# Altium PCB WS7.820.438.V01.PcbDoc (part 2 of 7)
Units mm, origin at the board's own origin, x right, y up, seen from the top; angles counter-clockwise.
Board outline 143.01 x 224 mm, 4 copper layers (Top Layer, G2, S3, Bottom Layer); 863 components, 638 nets, 2623 pads, 4664 vias.
Unrouted connection lines stored in the file: 16.
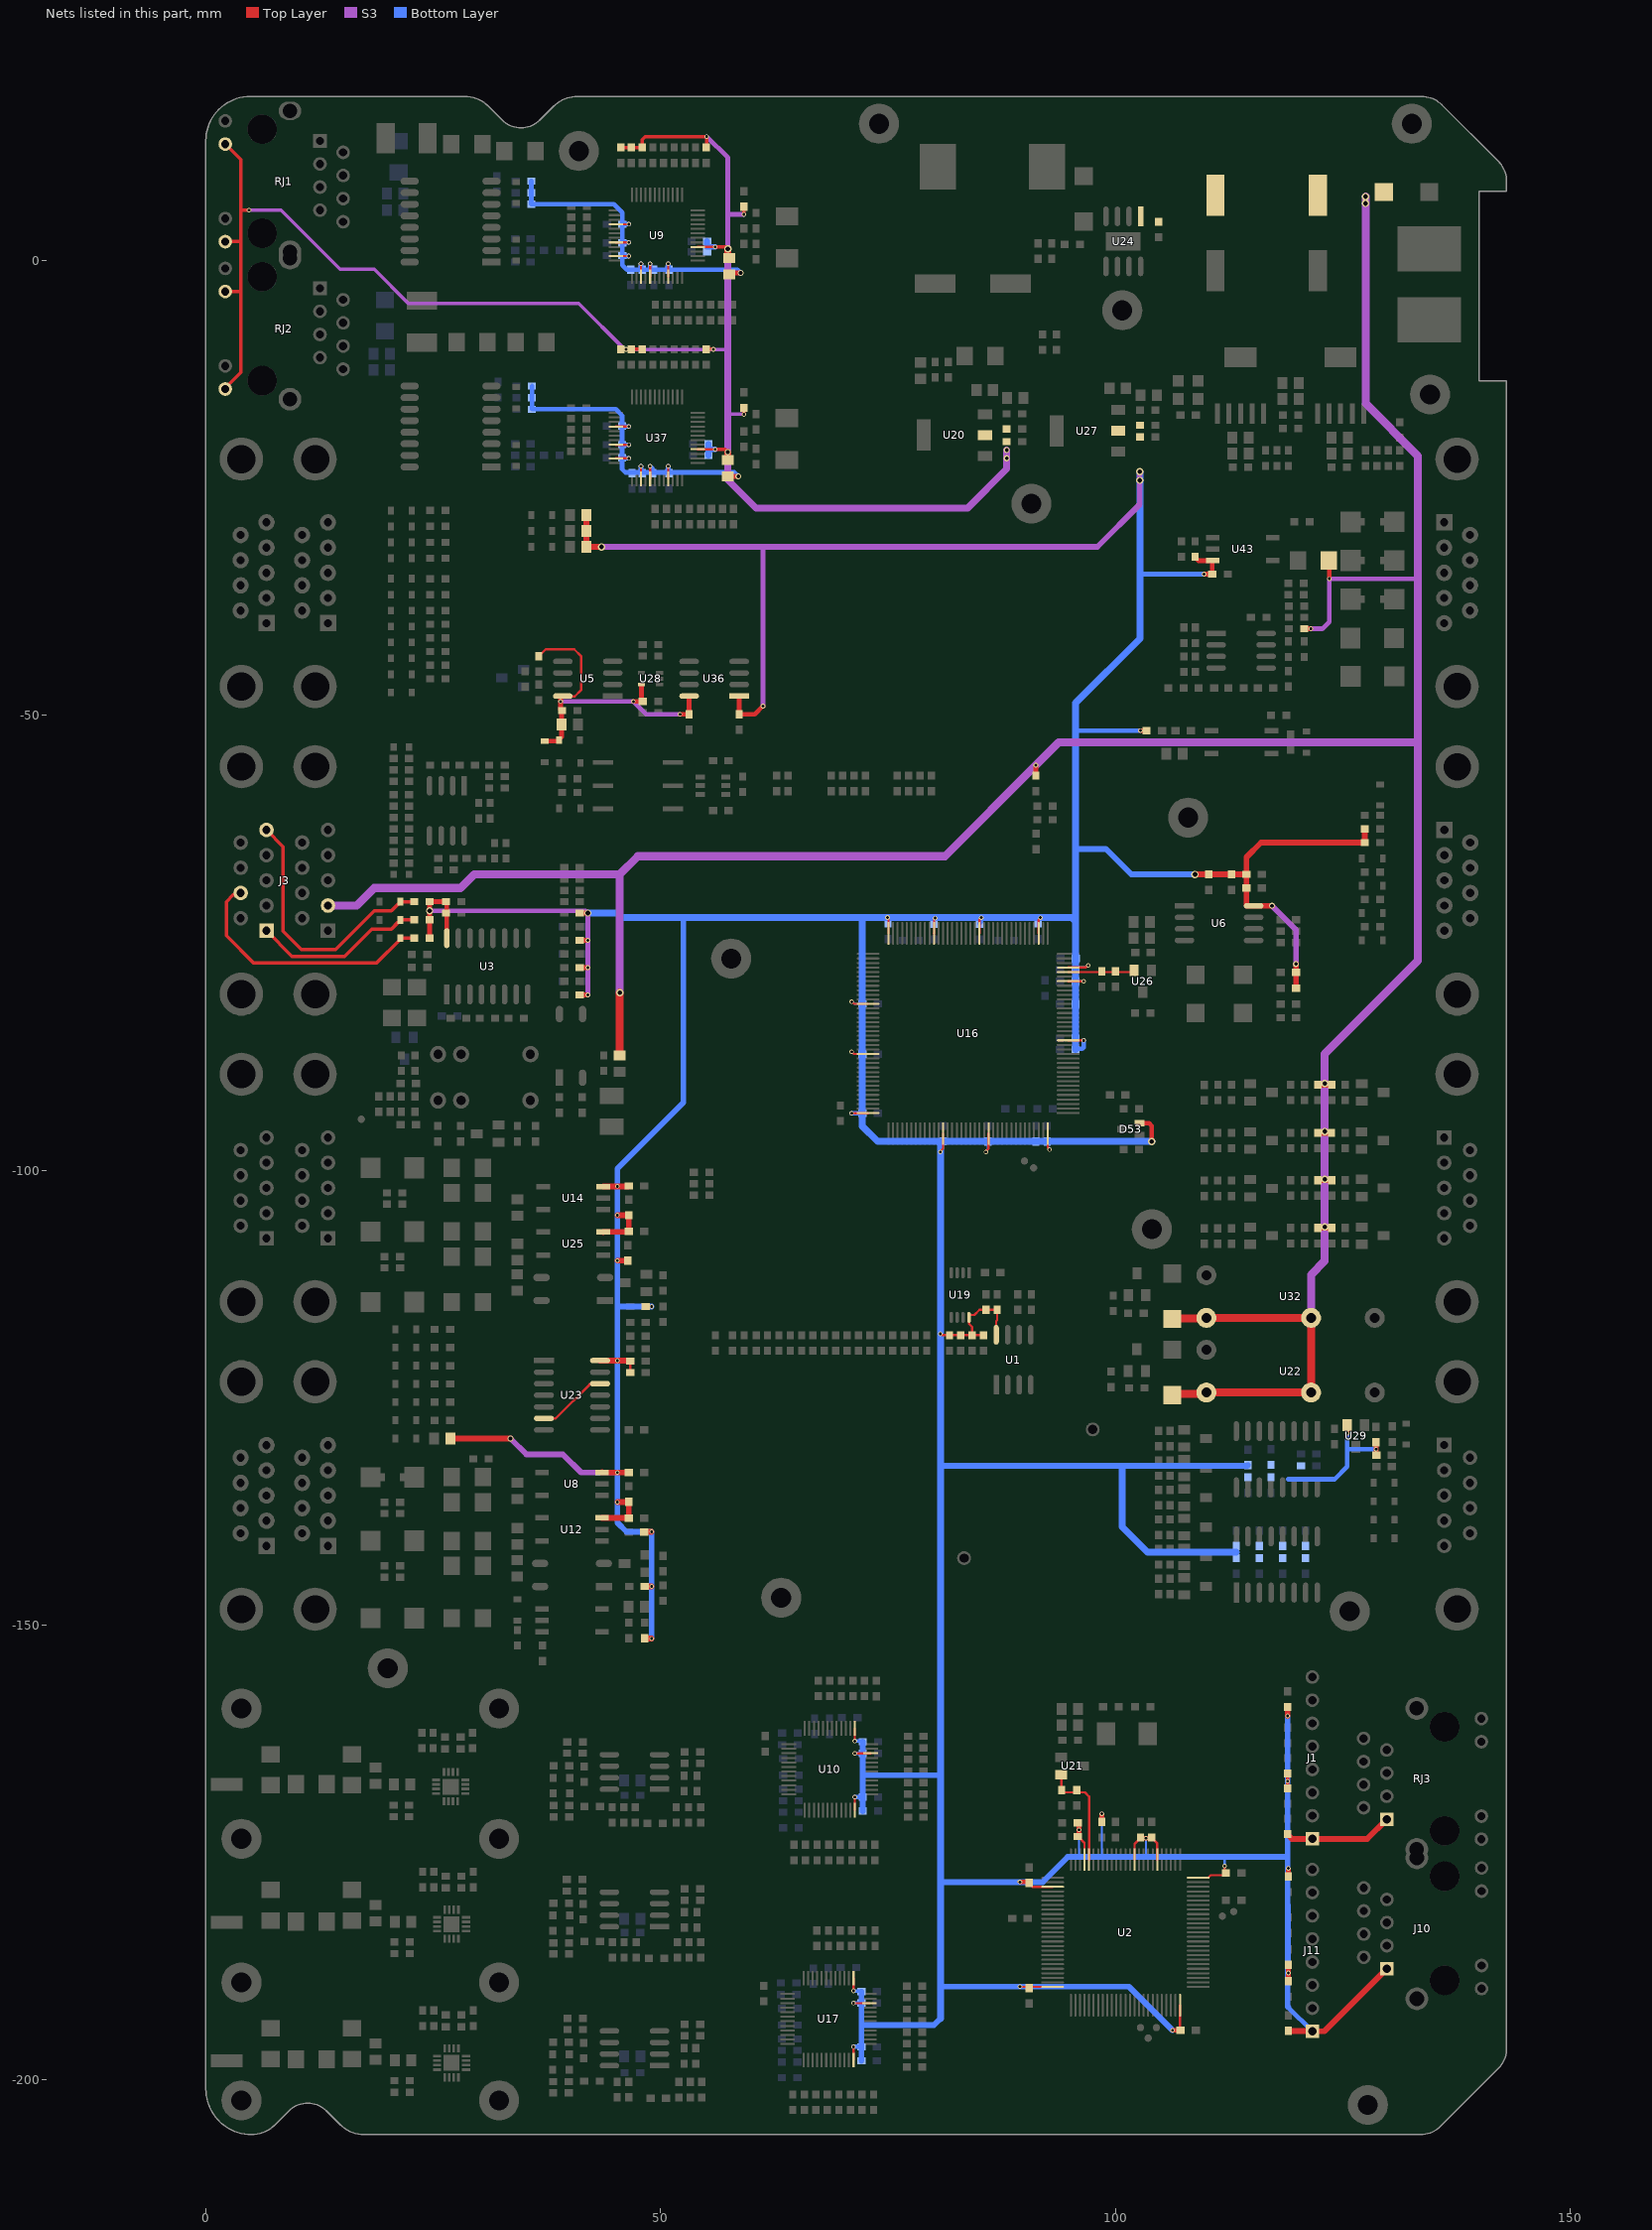
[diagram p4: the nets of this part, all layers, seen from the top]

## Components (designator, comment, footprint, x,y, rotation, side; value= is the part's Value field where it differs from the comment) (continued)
X2 "25M" CRY2SM-6R0X3R5 63.9,2.522 r270 top
X3 "40M" CRY4SM-5R0x7R0 111.403,-80.636 r180 top
X5 "25M" CRY2SM-6R0x3R5 63.886,-19.66 r270 top

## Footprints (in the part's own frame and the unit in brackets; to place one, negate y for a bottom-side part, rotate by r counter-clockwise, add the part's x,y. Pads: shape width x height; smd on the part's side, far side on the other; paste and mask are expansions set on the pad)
C0603#1 [mm]
  rect 0.9x0.8 smd: 1(-0.85,0) 2(0.85,0)
  silkscreen extent -1.47,-0.55 1.47,0.55
C0603#2 [mm]
  rect 0.9x0.8 smd: 1(0.85,0) 2(-0.85,0)
  silkscreen extent -1.47,-0.55 1.47,0.55
C0805#1 [mm]
  rect 1.1x1.3 smd: 1(-0.9,0) 2(0.9,0)
  silkscreen extent -1.57,-0.76 1.57,0.76
C0805#2 [mm]
  rect 1.2x1.3 smd: 1(-1.1,0) 2(1.1,0)
  silkscreen extent -1.88,-0.84 1.88,0.84
C1206 [mm]
  rect 1.8x2 smd: 1(-1.7,0) 2(1.7,0)
  silkscreen extent -2.79,-1.19 2.79,1.19
C1210 [mm]
  rect 1.8x2.6 smd: 1(-1.7,0) 2(1.7,0)
  silkscreen extent -2.82,-1.52 2.82,1.52
CR2032 [mm] "纽扣电池"
  round 1.524 hole 1: 1(10,0) 2(-10,0)
  silkscreen extent -12.85,-11.05 11.45,11.05
CRY2SM-6R0x3R5 [mm]
  rect 2x2.5 smd: 1(-2.3,0) 2(2.3,0)
  silkscreen extent -3.4,-2.03 3.4,1.97
CRY2SM-6R0X3R5 [mm]
  rect 2x2.5 smd: 1(-2.3,0) 2(2.3,0)
  silkscreen extent -3.4,-2.03 3.4,1.97
CRY4SM-5R0x7R0 [mm]
  rect 2x2 smd: 1(-2.6,-2.1) 2(2.6,-2.1) 3(2.6,2.1) 4(-2.6,2.1)
  silkscreen extent -3.81,-4.02 3.81,3.33
D1812 [mm]
  rect 2x3.3 smd: 1(-2.3,0) 2(2.3,0)
  silkscreen extent -3.48,-1.85 3.48,1.85
DB2TM-VM [mm] "DB2"
  rect 5x7 smd: 1(-3.9,0) 2(3.9,0)
  Top Overlay keep-out lines w0.1: -1.298,2.812 -5.698,2.812
  silkscreen extent -15.4,-1.19 15.4,19.81
DB9TM-RF#1 [mm] "90度弯针DB9，焊接在板子上"
  rect 1.6x1.6 hole 0.9: 1(0,0)
  round 1.6 hole 0.9: 2(-2.77,0) 3(-5.54,0) 4(-8.31,0) 5(-11.08,0) 6(-1.385,-2.84) 7(-4.155,-2.84) 8(-6.925,-2.84) 9(-9.695,-2.84)
  round 4.76 hole 3: 10(6.955,-1.42) 11(-18.035,-1.42)
  silkscreen extent -20.94,-16.92 9.86,1.48
DB9TM-RF#2 [mm] "90度弯针DB9，焊接在板子上"
  rect 1.8x1.8 hole 0.9: 1(0,0)
  round 1.8 hole 0.9: 2(-2.77,0) 3(-5.54,0) 4(-8.31,0) 5(-11.08,0) 6(-1.385,-2.84) 7(-4.155,-2.84) 8(-6.925,-2.84) 9(-9.695,-2.84)
  round 4.76 hole 3: 10(6.955,-1.42) 11(-18.035,-1.42)
  silkscreen extent -20.94,-16.92 9.86,1.48
DB9TM-RF-双胞胎#1 [mm] "90度弯针DB9，焊接在板子上"
  rect 1.6x1.6 hole 0.9: A1(5.54,-1.96) B1(5.54,4.8)
  round 1.6 hole 0.9: A2(2.77,-1.96) A3(0,-1.96) A4(-2.77,-1.96) A5(-5.54,-1.96) A6(4.155,-4.8) A7(1.385,-4.8) A8(-1.385,-4.8) A9(-4.155,-4.8) B2(2.77,4.8) B3(0,4.8) B4(-2.77,4.8) B5(-5.54,4.8) B6(4.155,1.96) B7(1.385,1.96) B8(-1.385,1.96) B9(-4.155,1.96)
  round 4.76 hole 3.1: A10(12.495,-4.72) A11(-12.495,-4.72) B10(12.495,3.38) B11(-12.495,3.38)
  silkscreen extent -15.4,-18.88 15.4,6.37
DB9TM-RF-双胞胎#2 [mm] "90度弯针DB9，焊接在板子上"
  rect 1.8x1.8 hole 0.9: A1(5.54,-1.96) B1(5.54,4.8)
  round 1.8 hole 0.9: A2(2.77,-1.96) A3(0,-1.96) A4(-2.77,-1.96) A5(-5.54,-1.96) A6(4.155,-4.8) A7(1.385,-4.8) A8(-1.385,-4.8) A9(-4.155,-4.8) B2(2.77,4.8) B3(0,4.8) B4(-2.77,4.8) B5(-5.54,4.8) B6(4.155,1.96) B7(1.385,1.96) B8(-1.385,1.96) B9(-4.155,1.96)
  round 4.76 hole 3.1: A10(12.495,-4.72) A11(-12.495,-4.72) B10(12.495,3.38) B11(-12.495,3.38)
  silkscreen extent -15.4,-18.88 15.4,6.37
DO-214AA [mm]
  rect 2.2x2.2 smd: 1(-2.4,0)
  rect 2.2x2.3 smd: 2(2.4,0)
  silkscreen extent -2.35,-1.97 2.35,1.97
DO-214AC [mm]
  rect 2x2 smd: 1(-2.5,0) 2(2.5,0)
  silkscreen extent -3.04,-1.49 3.04,1.49
ECAP2SM_10R4x10R4 [mm]
  rect 4.5x2 smd: 1(-4.15,0) 2(4.15,0)
  silkscreen extent -6.16,-5.21 5.08,5.21
G5NB-1A-E-DC24-20R4X7 [mm]
  round 2.2 hole 1.1: 1(-9.25,-2.35) 2(2.25,-2.35) 3(9.25,-2.35) 4(-9.25,2.35)
  silkscreen extent -10.41,-3.5 10.41,3.5
G5V-1-5VDC [mm]
  round 1.8 hole 1: 1(-5.08,-2.54) 2(-2.54,-2.54) 5(5.08,-2.54) 6(5.08,2.54) 9(-2.54,2.54) 10(-5.08,2.54)
  silkscreen extent -6.3,-3.81 6.3,3.8
L0603 [mm]
  rect 0.9x0.8 smd: 1(0.85,0) 2(-0.85,0)
  silkscreen extent -1.47,-0.55 1.47,0.55
L0805 [mm]
  rect 1.1x1.3 smd: 1(-0.9,0) 2(0.9,0)
  silkscreen extent -1.57,-0.76 1.57,0.76
L1206 [mm]
  rect 1.8x2 smd: 1(-1.7,0) 2(1.7,0)
  silkscreen extent -2.79,-1.19 2.79,1.19
LQFP100_0R5_14x14 [mm]
  rect 0.22x2.5 smd: 1(6.326,7.865)
  oval 0.22x2.5 smd: 2(5.826,7.865) 3(5.326,7.865) 4(4.826,7.865) 5(4.326,7.865) 6(3.826,7.865) 7(3.326,7.865) 8(2.826,7.865) 9(2.326,7.865) 10(1.826,7.865) 11(1.326,7.865) 12(0.826,7.865) 13(0.326,7.865) 14(-0.174,7.865) 15(-0.674,7.865) 16(-1.174,7.865) 17(-1.674,7.865) 18(-2.174,7.865) 19(-2.674,7.865) 20(-3.174,7.865) 21(-3.674,7.865) 22(-4.174,7.865) 23(-4.674,7.865) 24(-5.174,7.865) 25(-5.674,7.865) 51(-5.674,-8.135) 52(-5.174,-8.135) 53(-4.674,-8.135) 54(-4.174,-8.135) 55(-3.674,-8.135) 56(-3.174,-8.135) 57(-2.674,-8.135) 58(-2.174,-8.135) 59(-1.674,-8.135) 60(-1.174,-8.135) 61(-0.674,-8.135) 62(-0.174,-8.135) 63(0.326,-8.135) 64(0.826,-8.135) 65(1.326,-8.135) 66(1.826,-8.135) 67(2.326,-8.135) 68(2.826,-8.135) 69(3.326,-8.135) 70(3.826,-8.135) 71(4.326,-8.135) 72(4.826,-8.135) 73(5.326,-8.135) 74(5.826,-8.135) 75(6.326,-8.135)
  oval 2.5x0.22 smd: 26(-7.674,5.865) 27(-7.674,5.365) 28(-7.674,4.865) 29(-7.674,4.365) 30(-7.674,3.865) 31(-7.674,3.365) 32(-7.674,2.865) 33(-7.674,2.365) 34(-7.674,1.865) 35(-7.674,1.365) 36(-7.674,0.865) 37(-7.674,0.365) 38(-7.674,-0.135) 39(-7.674,-0.635) 40(-7.674,-1.135) 41(-7.674,-1.635) 42(-7.674,-2.135) 43(-7.674,-2.635) 44(-7.674,-3.135) 45(-7.674,-3.635) 46(-7.674,-4.135) 47(-7.674,-4.635) 48(-7.674,-5.135) 49(-7.674,-5.635) 50(-7.674,-6.135) 76(8.326,-6.135) 77(8.326,-5.635) 78(8.326,-5.135) 79(8.326,-4.635) 80(8.326,-4.135) 81(8.326,-3.635) 82(8.326,-3.135) 83(8.326,-2.635) 84(8.326,-2.135) 85(8.326,-1.635) 86(8.326,-1.135) 87(8.326,-0.635) 88(8.326,-0.135) 89(8.326,0.365) 90(8.326,0.865) 91(8.326,1.365) 92(8.326,1.865) 93(8.326,2.365) 94(8.326,2.865) 95(8.326,3.365) 96(8.326,3.865) 97(8.326,4.365) 98(8.326,4.865) 99(8.326,5.365) 100(8.326,5.865)
  silkscreen extent -5.89,-6.35 6.65,10.08
LQFP144_0R5_20x20 [mm]
  rect 2.5x0.22 smd: 1(-11,8.75)
  oval 2.5x0.22 smd: 2(-11,8.25) 3(-11,7.75) 4(-11,7.25) 5(-11,6.75) 6(-11,6.25) 7(-11,5.75) 8(-11,5.25) 9(-11,4.75) 10(-11,4.25) 11(-11,3.75) 12(-11,3.25) 13(-11,2.75) 14(-11,2.25) 15(-11,1.75) 16(-11,1.25) 17(-11,0.75) 18(-11,0.25) 19(-11,-0.25) 20(-11,-0.75) 21(-11,-1.25) 22(-11,-1.75) 23(-11,-2.25) 24(-11,-2.75) 25(-11,-3.25) 26(-11,-3.75) 27(-11,-4.25) 28(-11,-4.75) 29(-11,-5.25) 30(-11,-5.75) 31(-11,-6.25) 32(-11,-6.75) 33(-11,-7.25) 34(-11,-7.75) 35(-11,-8.25) 36(-11,-8.75) 73(11,-8.75) 74(11,-8.25) 75(11,-7.75) 76(11,-7.25) 77(11,-6.75) 78(11,-6.25) 79(11,-5.75) 80(11,-5.25) 81(11,-4.75) 82(11,-4.25) 83(11,-3.75) 84(11,-3.25) 85(11,-2.75) 86(11,-2.25) 87(11,-1.75) 88(11,-1.25) 89(11,-0.75) 90(11,-0.25) 91(11,0.25) 92(11,0.75) 93(11,1.25) 94(11,1.75) 95(11,2.25) 96(11,2.75) 97(11,3.25) 98(11,3.75) 99(11,4.25) 100(11,4.75) 101(11,5.25) 102(11,5.75) 103(11,6.25) 104(11,6.75) 105(11,7.25) 106(11,7.75) 107(11,8.25) 108(11,8.75)
  oval 0.22x2.5 smd: 37(-8.75,-11) 38(-8.25,-11) 39(-7.75,-11) 40(-7.25,-11) 41(-6.75,-11) 42(-6.25,-11) 43(-5.75,-11) 44(-5.25,-11) 45(-4.75,-11) 46(-4.25,-11) 47(-3.75,-11) 48(-3.25,-11) 49(-2.75,-11) 50(-2.25,-11) 51(-1.75,-11) 52(-1.25,-11) 53(-0.75,-11) 54(-0.25,-11) 55(0.25,-11) 56(0.75,-11) 57(1.25,-11) 58(1.75,-11) 59(2.25,-11) 60(2.75,-11) 61(3.25,-11) 62(3.75,-11) 63(4.25,-11) 64(4.75,-11) 65(5.25,-11) 66(5.75,-11) 67(6.25,-11) 68(6.75,-11) 69(7.25,-11) 70(7.75,-11) 71(8.25,-11) 72(8.75,-11) 109(8.75,11) 110(8.25,11) 111(7.75,11) 112(7.25,11) 113(6.75,11) 114(6.25,11) 115(5.75,11) 116(5.25,11) 117(4.75,11) 118(4.25,11) 119(3.75,11) 120(3.25,11) 121(2.75,11) 122(2.25,11) 123(1.75,11) 124(1.25,11) 125(0.75,11) 126(0.25,11) 127(-0.25,11) 128(-0.75,11) 129(-1.25,11) 130(-1.75,11) 131(-2.25,11) 132(-2.75,11) 133(-3.25,11) 134(-3.75,11) 135(-4.25,11) 136(-4.75,11) 137(-5.25,11) 138(-5.75,11) 139(-6.25,11) 140(-6.75,11) 141(-7.25,11) 142(-7.75,11) 143(-8.25,11) 144(-8.75,11)
  silkscreen extent -13.15,-9.19 9.19,9.19
PL2SM-12R5x12R5 [mm]
  rect 5x4 smd: 1(0,6) 2(0,-6)
  silkscreen extent -6.5,-6.5 6.5,6.5
QFN16_0R50_3X3 [mm]
  rect 0.9x0.3 smd: 1(-1.6,0.75) 2(-1.6,0.25) 3(-1.6,-0.25) 4(-1.6,-0.75) 9(1.6,-0.75) 10(1.6,-0.25) 11(1.6,0.25) 12(1.6,0.75)
  rect 0.3x0.9 smd: 5(-0.75,-1.6) 6(-0.25,-1.6) 7(0.25,-1.6) 8(0.75,-1.6) 13(0.75,1.6) 14(0.25,1.6) 15(-0.25,1.6) 16(-0.75,1.6)
  rect 1.75x1.75 smd: 17(0,0)
  silkscreen extent -2.04,-1.55 1.55,1.55
R0603 [mm]
  rect 0.9x0.8 smd: 1(-0.85,0) 2(0.85,0)
  silkscreen extent -1.47,-0.55 1.47,0.55
R0805 [mm]
  rect 1.1x1.3 smd: 1(-0.9,0) 2(0.9,0)
  silkscreen extent -1.57,-0.76 1.57,0.76
R1206 [mm]
  rect 1.8x2 smd: 1(-1.7,0) 2(1.7,0)
  silkscreen extent -2.79,-1.19 2.79,1.19
RJ45TH-1x1-2R54-LED#1 [mm]
  rect 1.5x1.5 hole 0.9: 1(-4.445,-1.27)
  round 1.5 hole 0.9: 2(-3.175,1.27) 3(-1.905,-1.27) 4(-0.635,1.27) 5(0.635,-1.27) 6(1.905,1.27) 7(3.175,-1.27) 8(4.445,1.27) 9(-6.63,-11.68) 10(-4.09,-11.68) 11(4.09,-11.68) 12(6.63,-11.68)
  round 2.5 hole 1.6: 13(-7.75,-4.57) 14(7.75,-4.57)
  round 3.25 hole 3.25 unplated: 15(-5.715,-7.62) 16(5.715,-7.62)
  silkscreen extent -7.94,-18.42 7.94,2.73
RJ45TH-1x1-2R54-LED#2 [mm]
  rect 1.5x1.5 hole 0.9: 1(-4.445,-1.27)
  round 1.5 hole 0.9: 2(-3.175,1.27) 3(-1.905,-1.27) 4(-0.635,1.27) 5(0.635,-1.27) 6(1.905,1.27) 7(3.175,-1.27) 8(4.445,1.27) 9(-6.63,-11.68) 10(-4.09,-11.68) 11(4.09,-11.68) 12(6.63,-11.68)
  oval 2.032x2.5 hole 1.6: 13(-7.75,-4.57)
  round 2.5 hole 1.6: 14(7.75,-4.57)
  round 3.25 hole 3.25 unplated: 15(-5.715,-7.62) 16(5.715,-7.62)
  silkscreen extent -7.94,-18.42 7.94,2.73
SC70-5-1R3x2R2 [mm]
  rect 0.8x0.4 smd: 1(-1,0.65) 2(-1,0) 3(-1,-0.65) 4(1,-0.65) 5(1,0.65)
  silkscreen extent -1.13,-1.12 0.44,1.46
SIP8TM-2R54 [mm] "Connector; Header; 8 Position"
  rect 1.5x1.5 hole 0.9: 1(0,0)
  round 1.5 hole 0.9: 2(2.54,0) 3(5.08,0) 4(7.62,0) 5(10.16,0) 6(12.7,0) 7(15.24,0) 8(17.78,0)
  silkscreen extent -1.37,-1.3 19.23,1.3
SMA-50KFD-4 [mm] "SMA-JB3C"
  rect 3.5x1.4 smd: 1(0,0.06)
  silkscreen extent 2.37,-6.29 15.9,6.41
SO6-1R27-4R55X3R7 [mm]
  rect 0.6x1.5 smd: 1(-1.27,-3.3) 3(1.27,-3.3) 4(1.27,3.3) 5(0,3.3) 6(-1.27,3.3)
  silkscreen extent -1.85,-2.27 1.85,2.27
SOD-323 [mm]
  rect 0.65x0.85 smd: 1(-1.15,0) 2(1.15,0)
  silkscreen extent -1.25,-0.76 1.27,0.76
SOD-523 [mm]
  rect 0.7x0.8 smd: 1(-0.85,0) 2(0.85,0)
  silkscreen extent -1.35,-0.55 1.35,0.55
SOIC8_1R27_3R9X4R9 [mm]
  rect 2.15x0.6 smd: 1(-2.75,1.905)
  oval 2.15x0.6 smd: 2(-2.75,0.635) 3(-2.75,-0.635) 4(-2.75,-1.905) 5(2.75,-1.905) 6(2.75,-0.635) 7(2.75,0.635) 8(2.75,1.905)
  silkscreen extent -3.02,-2.45 1.47,2.99
SOIC8_1R27_3R9x4R9 [mm]
  rect 2.15x0.6 smd: 1(-2.75,1.905)
  oval 2.15x0.6 smd: 2(-2.75,0.635) 3(-2.75,-0.635) 4(-2.75,-1.905) 5(2.75,-1.905) 6(2.75,-0.635) 7(2.75,0.635) 8(2.75,1.905)
  silkscreen extent -3.02,-2.45 1.47,2.99
SOIC8_1R27_3R9X4R9-1 [mm]
  rect 2.15x0.6 smd: 1(-2.75,1.905)
  oval 2.15x0.6 smd: 2(-2.75,0.635) 3(-2.75,-0.635) 4(-2.75,-1.905) 5(2.75,-1.905) 6(2.75,-0.635) 7(2.75,0.635) 8(2.75,1.905)
  rect 2x3.8 smd: 9(0,0)
  silkscreen extent -3.02,-2.45 1.47,2.99
SOIC8_1R27_5R3x5R3 [mm]
  rect 2.15x0.6 smd: 1(-3.8,1.905)
  oval 2.15x0.6 smd: 2(-3.8,0.635) 3(-3.8,-0.635) 4(-3.8,-1.905) 5(3.8,-1.905) 6(3.8,-0.635) 7(3.8,0.635) 8(3.8,1.905)
  silkscreen extent -4.07,-2.7 2.36,2.99
SOIC14-1R27-3R9x8R65 [mm]
  rect 2.2x0.6 smd: 1(-3.086,3.81)
  oval 2.2x0.6 smd: 2(-3.086,2.54) 3(-3.086,1.27) 4(-3.086,0) 5(-3.086,-1.27) 6(-3.086,-2.54) 7(-3.086,-3.81) 8(3.086,-3.81) 9(3.086,-2.54) 10(3.086,-1.27) 11(3.086,0) 12(3.086,1.27) 13(3.086,2.54) 14(3.086,3.81)
  silkscreen extent -3.39,-4.7 1.77,4.95
SOIC16-1R27-3R9X9R9 [mm]
  rect 2.2x0.6 smd: 1(-3.086,4.445)
  oval 2.2x0.6 smd: 2(-3.086,3.175) 3(-3.086,1.905) 4(-3.086,0.635) 5(-3.086,-0.635) 6(-3.086,-1.905) 7(-3.086,-3.175) 8(-3.086,-4.445) 9(3.086,-4.445) 10(3.086,-3.175) 11(3.086,-1.905) 12(3.086,-0.635) 13(3.086,0.635) 14(3.086,1.905) 15(3.086,3.175) 16(3.086,4.445)
  silkscreen extent -3.39,-5.16 1.82,5.59
SOIC16-1R27-3R9x9R9 [mm]
  rect 2.2x0.6 smd: 1(-3.086,4.445)
  oval 2.2x0.6 smd: 2(-3.086,3.175) 3(-3.086,1.905) 4(-3.086,0.635) 5(-3.086,-0.635) 6(-3.086,-1.905) 7(-3.086,-3.175) 8(-3.086,-4.445) 9(3.086,-4.445) 10(3.086,-3.175) 11(3.086,-1.905) 12(3.086,-0.635) 13(3.086,0.635) 14(3.086,1.905) 15(3.086,3.175) 16(3.086,4.445)
  silkscreen extent -3.39,-5.16 1.82,5.59
SOP16-1R27-7R11X12R7 [mm]
  rect 2x0.76 smd: 1(-4.5,4.445)
  oval 2x0.76 smd: 2(-4.5,3.175) 3(-4.5,1.905) 4(-4.5,0.635) 5(-4.5,-0.635) 6(-4.5,-1.905) 7(-4.5,-3.175) 8(-4.5,-4.445) 9(4.5,-4.445) 10(4.5,-3.175) 11(4.5,-1.905) 12(4.5,-0.635) 13(4.5,0.635) 14(4.5,1.905) 15(4.5,3.175) 16(4.5,4.445)
  silkscreen extent -4.84,-6.4 3.1,6.4
SOP16-1R27-7R11x12R7 [mm]
  rect 2x0.76 smd: 1(-4.5,4.445)
  oval 2x0.76 smd: 2(-4.5,3.175) 3(-4.5,1.905) 4(-4.5,0.635) 5(-4.5,-0.635) 6(-4.5,-1.905) 7(-4.5,-3.175) 8(-4.5,-4.445) 9(4.5,-4.445) 10(4.5,-3.175) 11(4.5,-1.905) 12(4.5,-0.635) 13(4.5,0.635) 14(4.5,1.905) 15(4.5,3.175) 16(4.5,4.445)
  silkscreen extent -4.84,-6.4 3.1,6.4
SOT23-3 [mm]
  rect 1.3x1 smd: 1(1.2,-0.95) 2(1.2,0.95) 3(-1.2,0)
  silkscreen extent -1.34,-1.5 1.2,1.5
SOT23-6 [mm]
  rect 1x0.55 smd: 1(-1.4,0.95) 2(-1.4,0) 3(-1.4,-0.95) 4(1.4,-0.95) 5(1.4,0) 6(1.4,0.95)
  silkscreen extent -1.52,-1.5 0.78,1.88
SOT-223 [mm]
  rect 1.1x1.55 smd: 1(-2.3,-3.375) 2(0,-3.375) 3(2.3,-3.375)
  rect 3.45x1.55 smd: 4(0,3.375)
  silkscreen extent -3.7,-3.65 3.35,1.85
SOT-223-6 [mm]
  rect 0.55x2.2 smd: 1(-2.54,-3.1) 2(-1.27,-3.1) 3(0,-3.1) 4(1.27,-3.1) 5(2.54,-3.1)
  rect 3.5x2.2 smd: 6(0,3.1)
  silkscreen extent -3.7,-3.65 3.35,1.7
SOT-323 [mm]
  rect 0.7x1.1 smd: 1(0,0) 2(1.3,0) 3(0.65,1.9)
  silkscreen extent -0.03,0 1.3,1.93
TLP181 [mm]
  rect 1.8x0.8 smd: 1(-3.5,1.27)
  oval 1.8x0.8 smd: 3(-3.5,-1.27) 4(3.5,-1.27) 6(3.5,1.27)
  silkscreen extent -3.78,-1.8 2.29,2.53
TP0R8 [mm]
  round 0.8 smd: 1(0,0)
  silkscreen extent -0.48,-0.48 0.48,0.48
TQFN48-0R5-7X7 [mm]
  rect 1.6x0.22 smd: 1(-4.5,2.75) 2(-4.5,2.25) 3(-4.5,1.75) 4(-4.5,1.25) 5(-4.5,0.75) 6(-4.5,0.25) 7(-4.5,-0.25) 8(-4.5,-0.75) 9(-4.5,-1.25) 10(-4.5,-1.75) 11(-4.5,-2.25) 12(-4.5,-2.75) 25(4.5,-2.75) 26(4.5,-2.25) 27(4.5,-1.75) 28(4.5,-1.25) 29(4.5,-0.75) 30(4.5,-0.25) 31(4.5,0.25) 32(4.5,0.75) 33(4.5,1.25) 34(4.5,1.75) 35(4.5,2.25) 36(4.5,2.75)
  rect 0.22x1.6 smd: 13(-2.75,-4.5) 14(-2.25,-4.5) 15(-1.75,-4.5) 16(-1.25,-4.5) 17(-0.75,-4.5) 18(-0.25,-4.5) 19(0.25,-4.5) 20(0.75,-4.5) 21(1.25,-4.5) 22(1.75,-4.5) 23(2.25,-4.5) 24(2.75,-4.5) 37(2.75,4.5) 38(2.25,4.5) 39(1.75,4.5) 40(1.25,4.5) 41(0.75,4.5) 42(0.25,4.5) 43(-0.25,4.5) 44(-0.75,4.5) 45(-1.25,4.5) 46(-1.75,4.5) 47(-2.25,4.5) 48(-2.75,4.5)
  silkscreen extent -4.72,-3.06 3.06,3.65
TSSOP8-0R65-3R0x3R0 [mil]
  rect 47.24x16 smd: 1(-96.5,38.4)
  oval 47.24x16 smd: 2(-96.5,12.8) 3(-96.5,-12.8) 4(-96.5,-38.4) 5(96.5,-38.4) 6(96.5,-12.8) 7(96.5,12.8) 8(96.5,38.4)
  silkscreen extent -103,-59 59,67
VPT85BB-01A-6SM-2R54-6R65X7R45 [mm]
  rect 0.5x2.2 smd: 1(2.54,3.85) 2(0,3.85) 3(-2.54,3.85) 4(-2.54,-3.85) 5(0,-3.85) 6(2.54,-3.85)
  Top Layer region: 2.54,-3.85 2.54,-3.85 2.54,-3.85 2.54,-3.85
  Top Layer region: 2.54,-3.85 2.54,-3.85 2.54,-3.85 2.54,-3.85
  Top Layer region: 2.54,-3.85 2.54,-3.85 2.54,-3.85 2.54,-3.85
  Top Layer region: -2.54,3.85 -2.54,3.85 -2.54,3.85 -2.54,3.85
  Top Layer region: 0,3.85 0,3.85 0,3.85 0,3.85
  Top Layer region: -2.54,3.85 -2.54,3.85 -2.54,3.85 -2.54,3.85
  Top Layer region: -2.54,3.85 -2.54,3.85 -2.54,3.85 -2.54,3.85
  silkscreen extent -3.32,-3.72 3.56,4.83

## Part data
BT1: "Multicell Battery"
C1 C2 C3 C4 C5 C6 C7 C8 C10 C12 C13 C15 C16 C17 C18 C20 C21 C25 C26 C27 C29 C31 C33 C34 C35 C36 C37 C38 C50 C51 C52 C54 C58 C59 C63 C65 C66 C67 C69 C70 C71 C73 C74 C75 C76 C77 C78 C81 C84 C85 C90 C91 C92 C93 C96 C97 C98 C99 C101 C102 C103 C104 C105 C106 C107 C108 C109 C110 C115 C123 C124 C125 C126 C130 C131 C139 C140 C141 C154 C155 C157 C158 C159 C160 C163 C169 C172 C173 C174 C178 C203 C207 C225 C227 C228 C229 C230 C231 C232 C1053 C2001 C2003 C2005 C2009 C2011 C2012 C2015 C2017 C2019 C2023 C2025 C2027 C2029 C2031 C2033 C2037 C2039 C2041: library part 0.1uF贴片电容, "贴片电容_GRM188R71H104KA01D_0.1uF±10%,50V,0603"
C9 C11 C32 C39 C53 C55 C60 C64 C68 C72 C79 C89 C100 C117 C138 C142 C171 C176 C179 C226 C233 C2013 C2028 C2042: library part 10uF贴片电容, "贴片电容_GRM188R60J106ME47D_10uF±20%,6.3V,0603"
C14 C86 C133 C177 C205 C1054: library part 1uF贴片电容, "贴片电容_GRM188R61A105KA61D_1uF±10%,10V,0603"
C19 C57 C87 C88 C95 C116 C128 C129 C132 C134 C175 C180 C181 C201 C202 C204 C2006 C2020 C2034: library part 10uF贴片电容, "贴片电容_GRM21BR61A106KE19L_10uF±10%,10V,0805"
C22: library part 10uF贴片电容, "0603,2.2UF,50V,±10％,X5R"
C23 C24: library part 10uF贴片电容, "贴片电容_UMK107BBJ225KA-T_2.2uF±110%,50V,0603", MPN="Taiyo Yuden"
C28 C43 C46 C82 C237 C240 C2010 C2026 C2040: library part 1000pF贴片电容, "贴片电容_GRM188R71H102KA01_1000pF±10%,50V,0603"
C30 C83 C94 C118 C119 C120 C121: "GRM188R71H104KA01D", MPN=MURATA
C40 C47 C234 C241: library part 0.1uF贴片电容, "C0603C103K5RAC_10nF±10%,50V,0603", MPN=KEMET
C41 C235: library part 27nF贴片电容, "贴片电容_22nF±5%,50V,0603"
C42 C44 C236 C238: library part 18pF贴片电容, "贴片电容_GRM1885C1H180JA01D_18pF±5%,50V,0603"
C45 C239: library part 1uF贴片电容, "GRM188R61C475K_4.7uF±10%,16V,0603", MPN=Murata
C48 C49: library part 10uF贴片电容, "贴片电容_1206B102K202NT_1206,1000PF/2KV", MPN=风华
C56 C162: library part 100uF/63V电解电容, "电解电容_VEJ101M1JTR-1010_100uF/63V,±20%,表贴10*10"
C61 C62: library part 20pF贴片电容, "贴片电容_GRM188C1H200JB01D_20pF±5%,50V,0603"
C80: library part 10uF贴片电容, "贴片电容_GRM32ER71H106KA12L_10uF±10%,50V,1210"
C111: library part 4.7UF, "0603,4.7UF,16V,±10％,X5R"
C112: library part 1UF, "0603,1UF,10V,±10％,X5R"
C122 C127: library part 0.1uF贴片电容
C164: library part 1000uF/16V电解电容, "电解电容_VE102M1CTR-1010_1000uF/16V,±20%,表贴10*10"
C242 C243: library part 10uF贴片电容, "贴片电容_1000pF/2KV"
C1061 C1068: library part 100pF贴片电容, "贴片电容_GRM185C1H101K_100pF±10%,50V,0603"
C2002 C2016 C2030: library part 1000pF贴片电容, "贴片电容_100pF±10%,50V,0603"
C2004 C2018 C2032: library part 10pF贴片电容, "GRM1885C1H390JA01D_39pF±5%,50V,0603"
C2007 C2021 C2035: library part 10pF贴片电容, "贴片电容_GRM1885C1H680JA01D_0603,68PF,50V,±5％,COG", MPN=Murata
C2008 C2022 C2036: library part 100pF贴片电容, "贴片电容_GRM2165C1H101JA01D_100pF±5%,50V,0805"
C2014 C2024 C2038: library part 10uF贴片电容
D1 D60 D61 D64: library part 肖特基整流二极管_SS36, "肖特基整流二极管_SS36_封装SMA,3A/60V"
D2 D20 D33: library part ESD5B5.0ST1G
D3 D4 D5 D6 D7 D8 D9 D10 D11 D12 D16 D21 D22 D27 D28 D29 D30 D31 D32 D35 D36 D37 D38 D39 D40 D41 D43 D44 D45 D47 D56 D57 D58 D68 D69 D71 D72 D73 D74: library part ESD5B5.0ST1G, "ESD_ESD3V3D3B_SOD-323,3.3V,双管"
D13: library part SM712, "ESD_ESD15VAPB_SOT23"
D14 D15: "TVS_ESD5B5.0ST1G_SOD-523"
D17: library part SM712, "ESD_ESDSM712_SOT23"
D18 D42 D54 D55 D65: library part ESD5B5.0ST1G, "ESD_ESD5V0D3B_SOD-323,5V,双管"
D19 D34 D46 D48 D49 D50 D51 D59 D66 D67 D70: library part SMBJ12CA, "TVS_SMBJ24CA_SMB封装"
D23 D24 D25 D26: "ESD_ESDLC3V3D3B _SOD-323封装"
D52 D62 D63: "二极管_SOD323"
D53: "TVS_BAT54CW_SOT323"
F1 F2: library part 自恢复保险丝_SMD020-1206, "自恢复保险丝_SMD020-1206"
FB1 FB2 FB3 FB6 FB8 FB10 FB11 FB18 FB19 FB21 FB22 FB23 FB24 FB33 L1 L2 L12: library part 0805贴片磁珠, "贴片磁珠_600R,0805"
FB4 FB5 FB7 FB9 FB13 FB14 FB15 FB16 FB17 FB20 FB26 FB27 FB28 FB29 FB30 FB31 FB32 FB36 FB1007: library part 0603贴片磁珠, "贴片磁珠_100R,0603"
FB12: library part 1206贴片磁珠, "贴片磁珠_30R,6A,1206"
FB34 FB35: library part 0603贴片磁珠
FV1 FV2: library part 4532-401-LF, "贴片陶瓷气体放电管_SMD1812-230C_1812,230V,2KA", MPN=Littelfuse
J1 J11: library part 8p-2.54单排母座, "连接器_单排排母座8p_直插,间距2.54mm", MPN=WS
J2 J4 J9 J12: library part DB9-90度弯针, "连接器_DB9母头_90度弯针"
J3 J5 J6 J8: library part 双胞胎DB9DB9母头, "连接器_双胞胎DB9DB9母头_90度弯针，间距15.88mm", MPN=亚当科技
J7: library part DB2公头座子, "连接器_DB2公头,电源接头"
J10 RJ1 RJ2 RJ3: library part RJ45弯脚带灯, "RJ45插座_1*1,带左黄右绿灯,弯脚", MPN=朱迅
L11: library part 100uH贴片功率电感, "贴片功率电感_SLF12575T-101M1R9-PF_100uH±20%,额定电流1.9A,12.5x12.5"
Q1 Q2 Q3 Q4 Q5 Q6 Q7 Q8 Q9 Q10 Q11 Q12 Q13 Q14 Q15: "NPN三极管_MMBT2222_表贴SOT23"
R1 R2 R3 R4 R5 R6 R7 R15 R17 R51 R58 R67 R69 R77 R81 R82 R89 R109 R120 R121 R143 R147 R148 R153 R155 R156 R160 R172 R217 R218 R219 R220 R228 R269 R271 R279 R283 R284 R303 R317 R325 R2015 R2035 R2054: library part 4.7K贴片电阻, "贴片电阻_4.7K±5%,0603"
R8 R10 R21 R28 R54 R83 R84 R85 R86 R87 R88 R157 R164 R180 R195 R196 R225 R254 R255 R256 R257 R258 R259 R260 R261 R262 R285 R286 R287 R288 R289 R290 R291 R292 R293 R294 R295 R296 R297 R298 R299 R300 R301 R2003 R2026 R2045: library part 1K贴片电阻, "贴片电阻_1K±5%,0603"
R9 R53 R55 R61 R103 R144 R146 R158 R161 R224 R263 R313 R314 R320 R321 R1026 R1038 R2008 R2012 R2014 R2019 R2028 R2030 R2034 R2038 R2046 R2048 R2052 R2057: library part 0Ω贴片电阻, "贴片电阻_0Ω±5%,0603"
R11 R12 R13 R14 R36 R41 R49 R52 R57 R127 R128 R129 R152 R176 R182 R185 R187 R198 R199 R200 R202 R203 R205 R206 R207 R209 R210 R211 R212 R221 R222 R309 R310 R311 R312 R2001 R2007 R2018 R2022 R2024 R2037 R2040 R2044 R2056 R2058 R2059: library part 0Ω贴片电阻
R16 R39 R40 R46 R105 R190 R315 R316 R340 R341 R342 R343 R344 R345 R346 R347 R348 R349 R350 R351 R352: library part 510Ω贴片电阻, "贴片电阻_510Ω±5%,0603"
R18 R33 R34 R38 R44 R331 R333 R335 R337 R339: library part 1.5K贴片电阻, "贴片电阻_4.7K±5%,0603"
R19 R20 R23 R24 R25 R26 R27 R29 R30 R32 R35 R42 R43 R45 R47 R48 R56 R59 R60 R68 R70 R71 R72 R90 R91 R92 R93 R94 R95 R96 R97 R98 R99 R100 R106 R107 R111 R112 R113 R114 R115 R116 R117 R118 R119 R122 R123 R124 R125 R126 R130 R131 R132 R133 R134 R135 R136 R137 R138 R139 R140 R141 R142 R151 R167 R168 R169 R170 R171 R173 R174 R175 R177 R178 R208 R213 R214 R215 R223 R229 R230 R231 R232 R233 R234 R235 R236 R237 R238 R239 R240 R241 R242 R243 R244 R245 R246 R247 R248 R249 R250 R251 R252 R253 R270 R272 R273 R274 R302 R318 R322 R326 R327 R328 R329: library part 30Ω贴片电阻, "贴片电阻_30Ω±5%,0603"
R22 R73 R78 R162 R165 R275 R280: library part 300Ω贴片电阻, "贴片电阻_300Ω±5%,0603"
R31 R37 R188 R192 R323 R324 R330 R332 R334 R336 R338: library part 33K贴片电阻
R50 R183 R184 R189 R191 R193 R194 R201 R204 R227 R308: library part 3K贴片电阻, "贴片电阻_3K±5%,1206"
R62 R64 R264 R266: library part 51Ω贴片电阻, "贴片电阻_49.9Ω±1%,0603"
R63 R65 R265 R267: library part 51Ω贴片电阻, "贴片电阻_82Ω±1%,0603"
R66 R104 R268: library part 10Ω贴片电阻, "贴片电阻_10Ω±5%,0603"
R74 R76 R276 R278 R2011 R2033 R2051: library part 75Ω贴片电阻, "贴片电阻_75Ω±5%,0805"
R75 R277: library part 1M贴片电阻, "贴片电阻_1M±5%,0603"
R79 R281: library part 75Ω贴片电阻, "贴片电阻_75Ω±5%,1206"
R80 R282: library part 12K贴片电阻, "贴片电阻_12.4K±1%,0603"
R101 R110 R163: library part 2K贴片电阻, "贴片电阻_2K±5%,0603"
R102 R108 R159: library part 6.2K贴片电阻, "贴片电阻_6.2K±5%,0603"
R145: library part 10K贴片电阻, "贴片电阻_10K±5%,0603"
R149 R154 R197 R306 R319: library part 1K贴片电阻
R150 R307: library part 300Ω贴片电阻, "0603,100Ω,±5％"
R166: library part 1.5K贴片电阻, "0603,681Ω,±1％"
R179: library part 12.4K贴片电阻, "贴片电阻_12.4K±1%,0603"
R181 R216: library part 1.5K贴片电阻, "贴片电阻_1.5K±5%,0603"
R186: library part 120Ω贴片电阻, "贴片电阻_120Ω±5%,0603"
R226: library part 6.2K贴片电阻, "贴片电阻_1K±5%,0603"
R304: library part 4.7KΩ, "0603,4.7KΩ,±1％"
R305: library part 51KΩ, "0603,51KΩ,±1%"
R1032 R1039: library part 1K贴片电阻, "贴片电阻_1K±1%,0603"
R1033 R1040: library part 4.7K贴片电阻, "贴片电阻_2K±1%,0603"
R2002 R2006 R2013 R2017 R2021 R2023 R2029 R2036 R2039 R2042 R2047 R2055: library part 430Ω贴片电阻
R2004 R2025: library part 56Ω贴片电阻, "贴片电阻_1206,180Ω,±5％"
R2005 R2020 R2041: library part 0Ω贴片电阻, "0603,7.87KΩ,±1％"
R2009 R2010 R2031 R2032: library part 56Ω贴片电阻, "贴片电阻_68Ω±5%,1206"
R2016 R2027 R2053: library part 0Ω贴片电阻, "0603,2.2KΩ,±1％"
R2043: library part 56Ω贴片电阻, "贴片电阻_75Ω±5%,1206"
R2049 R2050: library part 56Ω贴片电阻, "贴片电阻_100Ω±5%,1206"
SMA2001 SMA2002 SMA2003: "射频同轴连接器_SMA-50KFD-4"
T1 T2: "网络变压器_HX1188NL_百兆,SOIC16"
TP2 TP4 TP5 TP6 TP9 TP10 TP12 TP13: library part TP0.8mm, "表贴测试点0.8mm"
TR1: "推挽变压器_表贴,隔离电压1500VDC"
U1: "EEPROM_AT24C02N_SOIC8"
U2: library part STM32F103VET, "MCU_STM32F103VET6_32 bit, LQFP100"
U3: "双通道232收发器_MAX3232CSE_SOIC16"
U4: "继电器_G5V-1-5VDC", MPN=OMRON
U5: "差分收发器_SN65LBC184DR_SOIC8"
U6: "SPI存储芯片_W25Q64CVSSIG_SOIC8", MPN=WINBOND
U7: library part LM358
U8 U12 U14 U25 U41 U42 U43: "高速光耦合器_SO6封装,2.7~5.5V,3750Vrms"
U9 U37: "以太网控制器_W5500_LQFP48"
U10 U17: "模数转换芯片_ADS8411_16-Bit,2MSPS,QFN48"
U11 U13 U15: "光耦_TLP181"
U16: "LQFP144,32-bit Arm, 480MHz MCUs, 2MB Flash,  1 MB RAM, analog interfaces, crypto"
U18 U34: library part TPS73701DCQ, "LDO_TPS73701DCQ_1A输出,SOT223-6"
U19: "温度传感器_DS18B20U_uSOP8"
U20 U27: "LDO_LM1117S-3.3_1A输出,SOT223"
U21 U26: "LDO_REF3133AIDBZT_3.3V输出,10mA输出,SOT23-3"
U22 U32: "继电器_G5NB-1A-E-DC24"
U23: "3路或门_SN74HC4075_SOIC14"
U24: "稳压集成电路_LM2576HVDP-ADJ_3A输出,SOIC8"
U28: "单路非门_SN74AHC1G04DC_SC70-5"
U29 U30 U31 U33 U35: "P-MOS_Si2369DS-T1-GE3_SOT23"
U36: "双通道数字隔离器_ADuM1201A_SOIC8"
U38: "推挽式变压器驱动器_SOT23-6,输入2.8~6V"
U39 U40: library part TLP291-4, "光耦_TLP181"
U1007: "运算放大器_LM358_SOIC8"
U2001 U2003 U2005: "检波器_ADL5511ACPZ_DC~6GHz,LFCSP16"
U2002 U2006: library part OP284
U2004: library part LM358, "运算放大器_LM358_SOIC8"
X1: library part 8M贴片无源晶体, "贴片无源晶体_8MHz,封装6035"
X2: library part 25M贴片无源晶体, "贴片无源晶体_25MHz,30ppm,6035封装"
X3: library part 16M贴片有源晶振, "贴片有源晶振_40M,20ppm,封装5x7", MPN=KDS
X5: library part 8M贴片无源晶体, "贴片无源晶体_25MHz,封装6035"

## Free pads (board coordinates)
  round 4.4 hole 2.2: ""(3.906,-202.25) ""(3.906,-189.29) ""(3.906,-173.497) ""(3.906,-159.19) ""(20,-154.75) ""(32.239,-202.25) ""(32.239,-189.29) ""(32.239,-173.497) ""(32.239,-159.19) ""(41,12) ""(57.75,-76.75) ""(63.25,-147) ""(74,15) ""(90.75,-26.75) ""(100.75,-5.5) ""(104,-106.5) ""(108,-61.25) ""(125.75,-148.5) ""(127.75,-202.75) ""(132.58,15) ""(134.58,-14.75)

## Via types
v1: diameter 0.508, hole 0.305, Top Layer to Bottom Layer, tented both sides, 4404 vias
v2: diameter 0.508, hole 0.3, Top Layer to Bottom Layer, tented both sides, 200 vias
v3: diameter 0.813, hole 0.508, Top Layer to Bottom Layer, tented both sides, 31 vias
v4: diameter 0.457, hole 0.305, Top Layer to Bottom Layer, tented both sides, 10 vias
v5: diameter 0.66, hole 0.406, Top Layer to Bottom Layer, tented both sides, 9 vias
v6: diameter 0.762, hole 0.406, Top Layer to Bottom Layer, tented both sides, 6 vias
v7: diameter 0.711, hole 0.406, Top Layer to Bottom Layer, tented both sides, 4 vias

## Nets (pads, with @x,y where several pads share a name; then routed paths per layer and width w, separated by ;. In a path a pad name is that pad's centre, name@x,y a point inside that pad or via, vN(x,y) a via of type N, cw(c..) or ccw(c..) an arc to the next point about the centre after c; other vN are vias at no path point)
1Y: U23.6 U23.12 | length 7.8
  Top Layer w0.254: U23.6@37.164,-127.29 38.46,-127.29 42.204,-123.546 43.27,-123.546 U23.12@43.336,-123.48
3.3_1: D38.1 FB16.1 J3.A5 | length 29.4
  Top Layer w0.381: J3.A5@6.666,-62.617 8.5,-64.451 8.5,-73.75 10.5,-75.75 14.25,-75.75 18.5,-71.5 20.4,-71.5 21.165,-70.734 21.265,-70.734 21.4,-70.6 D38.1@21.4,-70.5 FB16.1@22.9,-70.5
3.3_2: D39.1 FB17.1 J3.A7 | length 28.8
  Top Layer w0.381: J3.A7@3.826,-69.542 3.593,-69.775 2.975,-69.775 2.25,-70.5 2.25,-74.25 5.25,-77.25 18.75,-77.25 21.4,-74.6 D39.1@21.4,-74.5 FB17.1@22.9,-74.5
3.3_3: D40.1 FB9.1 J3.A1 | length 19.1
  Top Layer w0.381: J3.A1@6.666,-73.697 9.469,-76.5 15.25,-76.5 18.25,-73.5 20.4,-73.5 21.165,-72.735 21.265,-72.735 21.4,-72.6 D40.1@21.4,-72.5 FB9.1@22.9,-72.5
3.3VADD: C33.2 C34.2 C35.2 C36.2 C37.2 C38.2 C39.2 FB1.2 R62.2 R64.2 R66.2 U9.4 U9.8 U9.11 U9.15 U9.17 U9.21 | length 46.1
  Top Layer w0.254: U9.11@45.092,0.463 v1(46.49,0.463) ; U9.8@45.092,1.963 v1(46.49,1.963) ; U9.4@45.092,3.963 v1(46.49,3.963) ; U9.15@47.842,-1.787 v1(47.842,-0.388) ; U9.17@48.842,-1.787 v1(48.842,-0.388) ; U9.21@50.842,-1.787 v1(50.842,-0.388)
  Top Layer w0.508: FB1.2@57.386,-1.408 57.397,-1.397 v5(58.801,-1.397)
  Bottom Layer w0.508: R62.2@35.775,8.693 R66.2@35.775,7.423 R64.2@35.775,6.153 44.875,6.153 45.788,5.239 C34.2@45.788,3.952 ; v1(46.49,0.463) 45.848,0.463 C36.2@45.788,0.523 ; v1(46.49,1.963) 45.832,1.963 C35.2@45.788,1.92 ; v1(46.49,3.963) 45.8,3.963 C34.2@45.788,3.952 ; v1(47.842,-0.388) 47.842,-0.896 C38.2@47.986,-1.04 ; v1(48.842,-0.388) 48.842,-1.04 ; v1(50.842,-0.388) 50.842,-0.975 C37.2@50.907,-1.04 ; v5(58.801,-1.397) 58.444,-1.04 C37.2@50.907,-1.04 ; C36.2@45.788,0.523 45.788,-0.562 46.267,-1.04 C39.2@46.716,-1.04 C38.2@47.986,-1.04 ; C36.2@45.788,0.523 C35.2@45.788,1.92 ; C35.2@45.788,1.92 C34.2@45.788,3.952 ; C38.2@47.986,-1.04 48.842,-1.04 ; 48.842,-1.04 C33.2@49.256,-1.04 50.038,-1.04 C37.2@50.907,-1.04
3.3VADD2: C227.2 C228.2 C229.2 C230.2 C231.2 C232.2 C233.2 FB6.2 R264.2 R266.2 R268.2 U37.4 U37.8 U37.11 U37.15 U37.17 U37.21 | length 45.3
  Top Layer w0.254: U37.11@45.092,-21.775 v1(46.49,-21.775) ; U37.8@45.092,-20.275 v1(46.49,-20.275) ; U37.4@45.092,-18.275 v1(46.49,-18.275) ; U37.15@47.842,-24.025 v1(47.842,-22.627) ; U37.17@48.842,-24.025 v1(48.842,-22.627) ; U37.21@50.842,-24.025 v1(50.842,-22.627)
  Top Layer w0.508: FB6.2@57.386,-23.76 57.397,-23.749 v5(58.547,-23.749)
  Bottom Layer w0.508: R264.2@35.845,-13.825 R268.2@35.845,-15.103 R266.2@35.845,-16.381 45.057,-16.381 45.763,-17.086 C231.2@45.763,-18.222 C231.2@45.763,-18.275 ; v1(46.49,-21.775) C232.2@45.763,-21.775 ; v1(46.49,-20.275) C228.2@45.763,-20.275 ; v1(46.49,-18.275) C231.2@45.763,-18.275 ; C229.2@47.842,-23.248 v1(47.842,-22.627) ; v1(48.842,-22.627) 49.129,-22.914 ; C227.2@50.832,-23.317 C227.2@50.842,-23.327 ; v1(50.842,-22.627) C227.2@50.842,-23.327 ; C227.2@50.907,-23.392 C227.2@50.842,-23.327 ; v5(58.547,-23.749) 58.115,-23.317 49.129,-23.317 46.126,-23.317 45.763,-22.954 C232.2@45.763,-21.775 ; C232.2@45.763,-21.775 C232.2@45.763,-21.725 C228.2@45.763,-20.275 ; C228.2@45.763,-20.275 C228.2@45.763,-20.254 C231.2@45.763,-18.275
3.3VCC: C1.2 C3.2 C4.2 C5.2 C6.2 C7.2 C8.2 C9.2 C11.2 C13.2 C14.1 C26.2 C27.2 C29.2 C50.2 C51.2 C54.2 C58.2 C59.2 C60.2 C65.2 C66.2 C67.2 C68.2 C69.2 C70.2 C71.2 C72.2 C103.2 C104.2 C105.2 C106.2 C107.2 C109.2 C115.2 C140.1 C141.2 C142.2 C154.2 C155.2 C157.2 C158.2 C159.2 C160.2 C169.2 C171.2 C177.2 C179.2 D53.2 FB2.2 FB4.2 FB5.2 FB8.2 FB9.2 FB16.2 FB17.2 FB18.2 FB19.2 FB20.2 FB36.2 J1.1 J10.1 J11.1 R1.2 R2.2 R3.2 R4.2 R5.2 R6.2 R7.2 R17.1 R18.1 R31.1 R34.1 R38.1 R51.1 R89.1 R120.1 R121.1 R143.2 R147.2 R148.2 R153.2 R155.2 R156.2 R172.2 R188.1 R192.1 R217.1 R218.1 R219.1 R220.1 R228.1 R317.1 R323.1 R324.1 R325.1 R330.1 R331.1 R332.1 R333.1 R334.1 R335.1 R336.1 R337.1 R338.1 R339.1 RJ3.1 U1.8 U2.6 U2.11 U2.22 U2.28 U2.50 U2.75 U2.100 U3.16 U6.8 U8.6 U10.24 U10.34 U10.37 U12.6 U14.6 U16.17 U16.30 U16.33 U16.39 U16.52 U16.62 U16.72 U16.84 U16.95 U16.108 U16.121 U16.131 U16.144 U17.24 U17.34 U17.37 U19.8 U23.14 U25.6 U27.2 U29.2 U36.1 U43.6 | length 965
  Top Layer w0.191: v1(74.933,-72.238) 74.933,-72.324 75.051,-72.442 U16.72@75.051,-73.987
  Top Layer w0.229: U17.24@71.204,-197.809 v1(71.204,-196.357) ; v1(71.204,-190.21) U17.37@71.204,-188.809 ; v1(71.207,-191.559) U17.34@72.954,-191.559 ; U10.24@71.344,-170.359 v1(71.344,-168.907) ; v1(71.344,-162.76) U10.37@71.344,-161.359 ; v1(71.347,-164.109) U10.34@73.094,-164.109
  Top Layer w0.254: R228.1@46.65,-122.25 C106.2@46.65,-121 46.7,-121 C106.2@46.973,-121.273 ; v1(71,-93.75) 71.006,-93.744 72.794,-93.744 U16.108@72.801,-93.737 ; v1(71,-87) 71.029,-87 71.266,-87.237 U16.95@72.801,-87.237 ; v1(71,-81.5) 71.029,-81.5 71.266,-81.737 U16.84@72.801,-81.737 ; U16.62@80.051,-73.987 80.068,-73.97 80.068,-72.493 80.183,-72.377 v1(80.183,-72.309) ; v1(80.75,-118) 80.819,-118 80.969,-118.15 R2.2@85.5,-118.15 ; v1(80.75,-98) 80.75,-97.931 81.051,-97.631 U16.121@81.051,-95.987 ; R3.2@84.25,-118.15 84.25,-117.25 83.904,-116.904 83.904,-116.199 U19.8@83.899,-116.194 83.899,-115.994 83.969,-115.924 84.483,-115.924 85.057,-115.35 R172.2@85.75,-115.35 C1.2@87,-115.35 87,-116.5 86.885,-116.615 U1.8@86.885,-118.103 ; U16.52@85.051,-73.987 85.068,-73.97 85.068,-72.501 85.25,-72.319 v1(85.25,-72.25) ; v1(85.75,-98) 85.75,-97.931 86.051,-97.631 U16.131@86.051,-95.987 ; v1(89.5,-189.75) 89.516,-189.766 93.081,-189.766 U2.50@93.096,-189.781 ; C58.2@90.4,-178.25 C58.2@90.5,-178.35 ; C58.2@90.45,-178.35 90.881,-178.781 U2.28@93.096,-178.781 ; U16.39@91.551,-73.987 91.551,-72.518 91.75,-72.319 v1(91.75,-72.25) ; U16.144@92.551,-95.987 92.551,-97.484 92.75,-97.683 v1(92.75,-97.75) ; U16.17@94.801,-85.737 94.807,-85.744 96.494,-85.744 v1(96.5,-85.75) ; U16.30@94.801,-79.237 94.807,-79.244 96.494,-79.244 v1(96.5,-79.25) ; U16.33@94.801,-77.737 96.698,-77.737 96.933,-77.502 v1(97.002,-77.502) ; C59.2@95.85,-171.75 C59.2@96,-171.9 ; C60.2@96,-173.1 C60.2@95.85,-173.25 95.9,-173.25 96.596,-173.946 U2.22@96.596,-175.781 ; U2.11@102.096,-175.781 102.096,-174.054 102.75,-173.4 C51.2@102.75,-173.35 C51.2@102.837,-173.437 ; C26.2@103.913,-173.437 C26.2@104,-173.35 104,-173.4 104.596,-173.996 U2.6@104.596,-175.781 ; U2.75@107.096,-191.781 107.096,-194.496 C54.2@107.15,-194.55 ; U2.100@109.096,-177.781 110.202,-177.781 110.484,-177.5 C50.2@111.9,-177.5 ; v1(112,-176.5) 112,-177.4 C50.2@111.9,-177.5 ; C50.2@112.15,-177.5 C50.2@111.9,-177.5
  Top Layer w0.381: R5.2@118.923,-167.95 v1(118.923,-167.156) R6.2@118.923,-166.316
  Top Layer w0.508: FB17.2@24.6,-74.5 FB16.2@24.6,-70.5 C14.1@26.4,-70.5 26.475,-70.575 C13.2@26.475,-71.75 ; C13.2@26.4,-71.75 26.492,-71.842 U3.16@26.492,-74.511 ; R18.1@41.1,-80.75 v1(42,-80.75) ; R121.1@41.1,-77.75 v1(42,-77.75) ; R120.1@41.1,-74.75 v1(42,-74.75) ; R17.1@41.1,-71.75 v3(42,-71.75) ; U36.1@58.632,-47.905 C109.2@58.632,-49.9 60.35,-49.9 v1(61.25,-49) ; v1(89.5,-178.25) C58.2@90.4,-178.25 ; C60.2@96,-173.1 v1(96,-172.5) C59.2@96,-171.9 ; R143.2@98.5,-171.65 v1(98.5,-170.75) ; D53.2@102.65,-94.85 103.702,-94.85 104,-95.148 v3(104,-96.85) ; v1(102.743,-51.689) R323.1@103.417,-51.689 ; C51.2@102.837,-173.437 v1(103.35,-173.437) C26.2@103.913,-173.437 ; v1(106.277,-194.55) C54.2@107.15,-194.55 ; R317.1@108.75,-32.6 108.75,-32.65 109.12,-33.02 U43.6@110.696,-33.02 ; v1(109.75,-34.5) C115.2@110.65,-34.5 110.65,-33.066 U43.6@110.696,-33.02 ; U43.6@110.7,-33.02 U43.6@110.696,-33.02 ; R148.2@119,-189.15 v1(119,-188.25) R155.2@119,-187.35 ; R156.2@119,-177.65 v1(119,-176.75) ; v1(125.476,-128.905) U29.2@125.476,-128.016 ; R153.2@128.651,-129.921 128.67,-129.94 128.67,-131.299 FB20.2@128.69,-131.318
  Top Layer w0.635: FB2.2@26.9,-129.25 26.9,-129.268 27.133,-129.5 v5(33.5,-129.5) ; FB19.2@41.825,-29.75 FB19.2@41.825,-30.075 ; FB19.2@41.825,-29.75 FB18.2@41.825,-28 ; FB19.2@42.05,-30.075 FB19.2@41.825,-30.075 ; U23.14@43.336,-120.94 v2(45.25,-120.94) C106.2@46.44,-120.94 ; v3(43.5,-31.5) FB8.2@41.825,-31.5 FB19.2@41.825,-30.075 ; U12.6@43.55,-138.23 43.56,-138.24 46.49,-138.24 C104.2@46.5,-138.25 R217.1@46.5,-136.45 46.45,-136.5 v2(45.25,-136.5) ; U8.6@43.55,-133.23 43.568,-133.248 45.095,-133.248 45.097,-133.25 v2(45.25,-133.25) C103.2@46.5,-133.25 ; U25.6@43.7,-106.805 43.718,-106.788 46.462,-106.788 C107.2@46.5,-106.75 R219.1@46.5,-104.95 v2(45.25,-104.95) ; U14.6@43.7,-101.805 43.718,-101.788 v2(45.25,-101.788) 46.462,-101.788 C105.2@46.5,-101.75 ; v2(45.25,-109.95) R220.1@46.4,-109.95 R220.1@46.4,-110 ; R218.1@48.2,-139.8 48.25,-139.75 v1(49,-139.75) ; R324.1@48.25,-151.5 v1(49,-151.5) ; R192.1@48.25,-145.75 v1(49,-145.75) ; v3(108.75,-67.5) R51.1@110.25,-67.5 R89.1@112.75,-67.5 C142.2@114.4,-67.5 ; v5(117.2,-70.95) U6.8@115.19,-70.95 114.45,-70.95 114.4,-70.9 C142.2@114.4,-67.5 ; R4.2@118.923,-172.984 118.923,-173.034 119.394,-173.505 J1.1@121.641,-173.505 127.677,-173.505 RJ3.1@129.824,-171.358 ; v1(118.923,-160) R7.2@118.923,-159.002 ; R147.2@119,-194.6 119.03,-194.63 121.611,-194.63 J11.1@121.641,-194.66 121.647,-194.654 122.971,-194.654 J10.1@129.84,-187.785 ; FB4.2@119.85,-80 C140.1@119.85,-78.25 v5(119.85,-77.341) ; R325.1@127.4,-62.5 FB36.2@127.4,-64 116,-64 114.4,-65.6 C142.2@114.4,-67.5
  S3 w0.508: v3(24.6,-71.5) 41.75,-71.5 v3(42,-71.75) v1(42,-74.75) v1(42,-77.75) v1(42,-80.75) ; 60.918,-31.5 61,-31.5 ; v1(61.25,-49) 61.25,-31.5
  S3 w0.635: v5(33.5,-129.5) 35.25,-131.25 39.25,-131.25 41.25,-133.25 v2(45.25,-133.25) ; v3(43.5,-31.5) 60.918,-31.5 ; 61,-31.5 98,-31.5 102.679,-26.821 v3(102.679,-24.19) v3(102.679,-23.25) ; v5(117.2,-70.95) 119.85,-73.6 v5(119.85,-77.341)
  Bottom Layer w0.254: v1(71,-87) 71.029,-87 71.266,-87.237 71.902,-87.237 C154.2@72.036,-87.103 ; v1(71,-81.5) 71.069,-81.5 71.306,-81.737 C158.2@72.182,-81.737 ; v1(80.75,-98) v1@80.75,-97.969 ; C159.2@81.051,-96.85 C159.2@81.051,-96.837 ; v1(85.75,-98) 85.75,-97.931 86,-97.681 C160.2@86,-96.85 ; C4.2@92.5,-96.85 92.551,-96.901 92.551,-97.482 92.75,-97.681 v1(92.75,-97.75) ; C7.2@95.6,-85.5 C7.2@95.85,-85.75 ; C27.2@95.6,-79.25 v1(96.5,-79.25) ; C8.2@95.6,-78 95.873,-77.727 96.709,-77.727 96.933,-77.502 v1(97.002,-77.502) ; 96,-175.5 v1(96,-172.5) ; 98.5,-175.5 v1(98.5,-170.75) ; v1(103.35,-173.437) 103.35,-175.35 103.5,-175.5 ; v1(112,-176.5) 112,-175.5
  Bottom Layer w0.381: v1(71.204,-190.21) 72.005,-190.21 C71.2@72.076,-190.282 ; v1(71.207,-191.559) 72.069,-191.559 C70.2@72.076,-191.552 ; v1(71.344,-162.76) 72.145,-162.76 C67.2@72.216,-162.832 ; v1(71.347,-164.109) 72.209,-164.109 C66.2@72.216,-164.102
  Bottom Layer w0.508: v1(71,-93.75) 71.013,-93.737 C155.2@72.182,-93.737 ; v1(71.204,-196.357) 72.056,-196.357 C69.2@72.076,-196.378 ; v1(71.344,-168.907) 72.196,-168.907 C65.2@72.216,-168.928 ; C154.2@72.036,-87.103 C154.2@72.182,-87.249 ; C6.2@85.051,-72.937 85.051,-72.887 85.197,-72.741 85.197,-72.303 v1(85.25,-72.25) ; C11.2@95.6,-86.75 95.688,-86.662 96.366,-86.662 96.5,-86.528 v1(96.5,-85.75) ; 95.6,-51.651 95.638,-51.689 v1(102.743,-51.689) ; 102.679,-34.431 102.748,-34.5 v1(109.75,-34.5) ; 119,-192.019 J11.1@121.641,-194.66 ; v1(119,-188.25) 119,-180.75 ; 118.999,-133.985 124.079,-133.985 125.476,-132.588 125.476,-130.683 ; v1(125.476,-128.905) 125.476,-130.683 ; v1(128.651,-130.683) 125.476,-130.683
  Bottom Layer w0.635: v1(49,-151.5) v1(49,-145.75) v1(49,-139.75) 46.25,-139.75 45.25,-138.75 v2(45.25,-136.5) v2(45.25,-133.25) v2(45.25,-120.94) 45.25,-115 ; v1(49,-115) 45.25,-115 ; 52.5,-72.25 52.5,-92.575 45.25,-99.825 v2(45.25,-101.788) v2(45.25,-104.95) v2(45.25,-109.95) 45.25,-115 ; C72.2@72.076,-197.902 C69.2@72.076,-196.378 72.076,-193.965 ; C71.2@72.076,-190.282 C70.2@72.076,-191.552 72.076,-193.965 ; C68.2@72.216,-170.452 C65.2@72.216,-168.928 72.216,-166.515 ; C67.2@72.216,-162.832 C66.2@72.216,-164.102 72.216,-166.515 ; 80.75,-193.25 80.035,-193.965 72.076,-193.965 ; 80.75,-189.75 v1(89.5,-189.75) 101.477,-189.75 v1(106.277,-194.55) ; 80.75,-166.515 72.216,-166.515 ; 80.75,-132.5 114.49,-132.5 114.554,-132.436 R338.1@114.554,-132.422 ; 80.978,-178.25 v1(89.5,-178.25) 92,-178.25 94.75,-175.5 96,-175.5 98.5,-175.5 103.5,-175.5 112,-175.5 118.923,-175.5 ; 95.6,-64.695 98.945,-64.695 101.75,-67.5 v3(108.75,-67.5) ; v1(118.923,-160) v1(118.923,-167.156) 118.923,-173.505 ; 119,-192.019 118.923,-191.942 118.923,-175.5 ; J1.1@121.641,-173.505 118.923,-173.505 ; 118.923,-175.5 118.923,-173.505
  Bottom Layer w0.762: v3(42,-71.75) 45.25,-71.75 45.75,-72.25 52.5,-72.25 66.592,-72.25 66.604,-72.238 72,-72.238 ; v1(80.183,-72.309) 80.155,-72.309 v1@80.097,-72.25 ; 80.75,-193.25 80.75,-189.75 80.75,-166.515 80.75,-132.5 v1(80.75,-118) ; v1@80.75,-117.986 v1(80.75,-98) ; v1@80.75,-97.969 80.75,-97.099 80.501,-96.85 ; 95.377,-72.473 95.154,-72.25 v1(91.75,-72.25) v1(85.25,-72.25) v1@80.097,-72.25 ; C11.2@95.6,-86.75 R1.2@95.6,-81.75 C27.2@95.6,-79.25 C8.2@95.6,-78 95.6,-64.695 95.6,-51.651 95.6,-48.65 102.679,-41.571 102.679,-34.431 v3(102.679,-24.19) v3(102.679,-23.25) ; 100.75,-132.732 100.75,-139.231 103.505,-141.986 113.284,-141.986 ; v3(104,-96.85) C4.2@92.5,-96.85 C160.2@86,-96.85 81.051,-96.85 80.501,-96.85 ; 72,-72.238 72.182,-72.42 C158.2@72.182,-81.737 C154.2@72.182,-87.249 C155.2@72.182,-93.737 72.182,-95.182 73.85,-96.85 80.501,-96.85 ; 72,-72.238 v1(74.933,-72.238) 80.084,-72.238 v1@80.097,-72.25
3.3VCC_1: C31.2 C32.2 C86.2 C89.2 C225.2 C226.2 FB1.1 FB6.1 R67.2 R69.2 R77.2 R81.2 R82.2 R269.2 R271.2 R279.2 R283.2 R284.2 RJ1.10 RJ1.12 RJ2.10 RJ2.12 U9.28 U20.2 U37.28 | length 198.2
  Top Layer w0.254: U37.28@54.092,-20.775 v1(55.982,-20.775) ; U9.28@54.092,1.463 v1(55.982,1.463)
  Top Layer w0.381: RJ2.12@2.14,-14.157 RJ2.12@2.14,-14.149 2.14,-14.023 3.848,-12.315 3.848,5.5 ; RJ2.10@2.14,-3.437 3.848,-3.437 ; RJ1.12@2.14,2.052 3.827,2.052 ; RJ1.10@2.14,12.772 3.848,11.064 3.848,5.5 ; v1(4.75,5.5) 3.848,5.5 ; R279.2@45.612,-9.785 v1(46.196,-9.785) R283.2@46.786,-9.785 R284.2@47.961,-9.785 ; R77.2@45.612,12.402 R81.2@46.786,12.402 R82.2@47.961,12.402 47.961,13.253 48.304,13.596 v1(55.06,13.596) 55.06,12.453 R67.2@55.01,12.402 ; R269.2@55.01,-9.785 v1@55.785,-9.785 ; v1(55.982,-20.775) 57.08,-20.775 v5(57.386,-21.082) ; v1(55.982,1.463) 57.193,1.463 v3(57.386,1.27) ; v1(59.142,-16.928) R271.2@59.142,-16.217 ; v1(59.142,5.04) R69.2@59.142,5.881
  Top Layer w0.762: FB6.1@57.386,-21.96 v5(57.386,-21.082) ; v3(57.386,1.27) 57.386,0.537 FB1.1@57.658,0.265
  S3 w0.381: v1(4.75,5.5) 8.25,5.5 14.75,-1 18.5,-1 22.25,-4.75 41,-4.75 46.035,-9.785 v1(46.196,-9.785) 46.208,-9.797 v1(55.797,-9.797) 57.361,-9.797 ; 57.386,-17.018 57.476,-16.928 v1(59.142,-16.928)
  S3 w0.508: v1(55.06,13.596) 57.386,11.27 v3(57.386,1.27) ; 57.474,5.04 v1(59.142,5.04)
  S3 w0.762: v3(57.386,1.27) 57.386,-17.018 v5(57.386,-21.082) 57.386,-24.136 60.5,-27.25 83.75,-27.25 88.047,-22.953 v5(88.047,-20.871)
  Bottom Layer w0.635: C32.2@55.102,2.09 55.102,1.467 55.106,1.463 v1(55.982,1.463) ; C226.2@55.254,-21.456 55.254,-20.828 ; C225.2@55.254,-20.186 55.254,-20.828 ; v1(55.982,-20.775) 55.307,-20.775 55.254,-20.828
  other v5: 88.047,-21.76
3.3VCC_REF: C174.2 C176.2 U16.32 U26.2 | length 7.3
  Top Layer w0.254: U16.32@94.801,-78.237 98.68,-78.237 101.863,-78.237 U26.2@102.05,-78.05
3.3VCC_REF_1: C102.2 C117.2 U2.21 U21.2 | length 12.2
  Top Layer w0.254: U21.2@94.15,-166.55 U21.2@94.05,-166.45 94.05,-168.373 94.077,-168.4 95.75,-168.4 96.65,-168.4 97.096,-168.846 U2.21@97.096,-175.781
5V_S: C19.2 C20.2 C108.2 C110.2 D18.1 D62.1 R44.1 U5.8 U28.5 U36.8 | length 38
  Top Layer w0.254: R44.1@36.606,-43.519 36.606,-43.469 36.879,-43.196 36.929,-43.196 37.375,-42.75 40.5,-42.75 41.25,-43.5 41.25,-47.25 40.558,-47.942 U5.8@39.1,-47.942
  Top Layer w0.508: D62.1@37.25,-52.85 38.779,-52.85 38.85,-52.779 D18.1@38.85,-52.75 38.85,-52.65 39.1,-52.4 C19.2@39.1,-51 39.1,-49.5 39.104,-49.5 39,-49.396 39,-47.942 39.042,-47.899 U5.8@39.234,-47.899 ; v1(47,-48.5) C108.2@48.028,-48.5 ; 47.88,-47.5 47.882,-47.502 ; U28.5@47.882,-46.65 47.882,-47.502 ; C108.2@48.032,-48.5 C108.2@48.028,-48.5 ; v1(52.132,-49.9) C110.2@53.132,-49.9 U36.8@53.132,-47.905 ; 47.882,-47.502 47.882,-48.354 C108.2@48.028,-48.5
  S3 w0.508: v1(39,-48.5) v1(47,-48.5) 48.4,-49.9 v1(52.132,-49.9) v1@52.117,-49.915
24VIN: C56.1 C162.1 C163.2 D60.2 D61.2 D64.2 FB29.2 FB30.2 FB31.2 FB32.2 FB1007.1 J3.B2 L1.1 R179.1 R254.2 R255.2 R292.2 R293.2 R308.2 U22.1 U22.2 U24.1 U32.1 U32.2 | length 343.3
  Top Layer w0.508: R179.1@91.25,-56.65 v1(91.25,-55.5) ; FB1007.1@120.75,-40.5 v1(121.5,-40.5) ; R308.2@123.45,-33 123.5,-33.05 v1(123.5,-35)
  Top Layer w0.635: R292.2@122.25,-95.9 FB31.2@123.75,-95.9 ; R254.2@122.27,-106.36 FB29.2@123.77,-106.36 ; R255.2@122.27,-101.11 FB30.2@123.77,-101.11 ; R293.2@122.27,-90.61 FB32.2@123.77,-90.61
  Top Layer w0.889: L1.1@45.5,-87.41 v3(45.5,-80.5) ; D60.2@106.25,-124.75 106.4,-124.6 109.85,-124.6 U22.1@110,-124.45 U22.2@121.5,-124.45 U32.2@121.5,-116.25 U32.1@110,-116.25 ; D61.2@106.25,-116.37 106.31,-116.31 U32.1@109.94,-116.31
  S3 w0.508: v1(121.5,-40.5) 122.75,-40.5 123.5,-39.75 v1(123.5,-35) 133.25,-35 ; 133.214,-39.565 133.25,-39.6
  S3 w0.889: J3.B2@13.426,-70.927 16.573,-70.927 18.5,-69 28,-69 29.514,-67.486 45.5,-67.486 ; v3(45.5,-80.5) 45.5,-67.486 ; U32.2@121.5,-116.25 121.5,-111.5 123,-110 v3(123,-106.25) v3(123,-101) v3(123,-95.75) v3(123,-90.5) 123,-87.25 133.25,-77 133.25,-53.151 ; v3(127.5,7) v3(127.5,6.25) 127.5,-15.75 133.25,-21.5 133.25,-35 133.25,-39.6 133.25,-53.151 ; 45.5,-67.486 47.486,-65.5 81.25,-65.5 v1(91.25,-55.5) 93.75,-53 133.099,-53 133.25,-53.151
